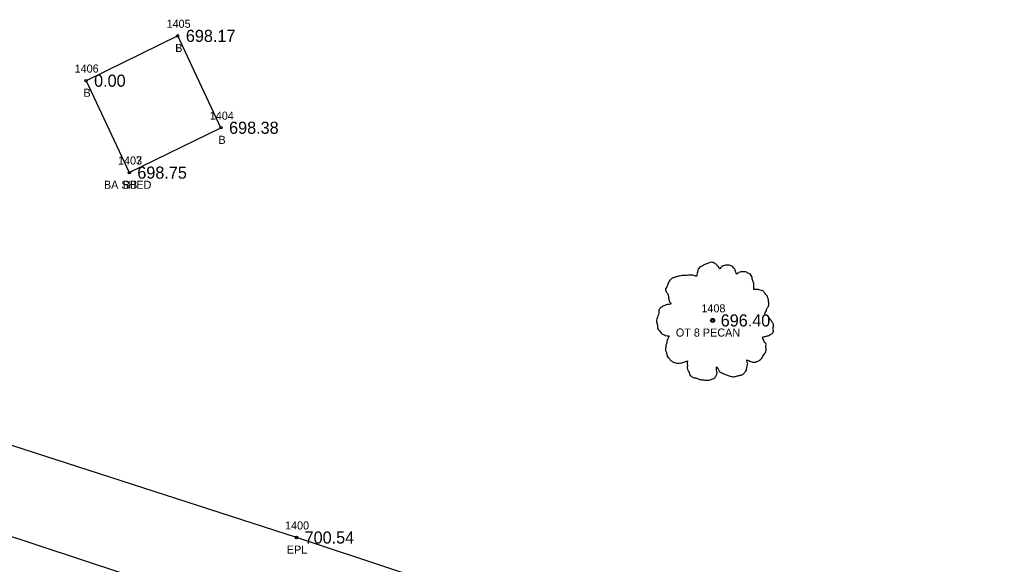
# Model space of a CAD drawing. Extents: x 1655137 to 1657928, y 1003994 to 1005407.
# Drawn here: x 1655718.8 to 1655840.3, y 1004839 to 1004906.5 of the extents above; entities that cross this region are included whole.
import ezdxf

# ---------------------------------------------------------------- set-up
doc = ezdxf.new("R2010")
doc.units = 0
for name, color, linetype in [('RD_EX_Bldg', 7, 'Continuous'), ('RD_EX_Bldg_txCode', 7, 'Continuous'), ('RD_EX_Road', 7, 'Continuous'), ('RD_EX_Road_txCode', 7, 'Continuous'), ('RD_EX_TX_Bldg_ELEV', 7, 'Continuous'), ('RD_EX_TX_Road_ELEV', 7, 'Continuous'), ('RD_EX_TX_VEG_ELEV', 7, 'Continuous'), ('RD_EX_VEG', 7, 'Continuous'), ('RD_EX_VEG_txCode', 7, 'Continuous'), ('RD_HC_Cl', 7, 'Continuous'), ('RD_SMD_Locator', 7, 'Continuous')]:
    doc.layers.add(name, color=color, linetype=linetype)

msp = doc.modelspace()

# ---------------------------------------------------------------- linework, layer by layer
at = {"layer": 'RD_EX_Bldg'}
msp.add_lwpolyline([(1655732.38, 1004887.51), (1655743.74, 1004893.07), (1655738.39, 1004904.45), (1655727.03, 1004898.9), (1655732.38, 1004887.51)], dxfattribs=at)
at = {"layer": 'RD_EX_Road'}
msp.add_lwpolyline([(1656365.12, 1004639.99), (1656336.04, 1004649.34), (1656302.55, 1004660.37), (1656279.15, 1004668.23), (1656240.07, 1004681.05), (1656188.23, 1004698.03), (1656166.72, 1004705.51), (1656141.16, 1004714.06), (1656093.11, 1004730.11), (1656044.16, 1004746.75), (1655996.36, 1004762.45), (1655947.2, 1004778.68), (1655899.09, 1004794.03), (1655850.62, 1004809.99), (1655801.91, 1004826.1), (1655753.09, 1004842.31), (1655704.25, 1004858.1)], dxfattribs=at)
at = {"layer": 'RD_EX_VEG'}
for centre, radius in [((1655804.6, 1004869.2), 0.25), ((1655804.59, 1004869.19), 0.0001)]:
    msp.add_circle(centre, radius, dxfattribs=at)
for points in [[(1655804.73, 1004876.37), (1655804.43, 1004876.4), (1655804.11, 1004876.3), (1655803.86, 1004876.2), (1655803.63, 1004876.12), (1655803.41, 1004876.02), (1655803.11, 1004875.85), (1655802.88, 1004875.65), (1655802.76, 1004875.4), (1655802.71, 1004875.17), (1655802.66, 1004874.9), (1655802.66, 1004874.72), (1655802.53, 1004874.7), (1655802.38, 1004874.72), (1655802.13, 1004874.8), (1655801.88, 1004874.8), (1655801.63, 1004874.8), (1655801.28, 1004874.77), (1655800.93, 1004874.77), (1655800.66, 1004874.72), (1655800.33, 1004874.67), (1655799.96, 1004874.55), (1655799.61, 1004874.42), (1655799.31, 1004874.17), (1655799.06, 1004873.7), (1655798.93, 1004873.35), (1655798.78, 1004873.1), (1655798.93, 1004872.65), (1655799.11, 1004872.3), (1655799.13, 1004872.1), (1655799.21, 1004871.67), (1655799.31, 1004871.45), (1655799.43, 1004871.25), (1655799.36, 1004871.22), (1655798.98, 1004871.17), (1655798.68, 1004871.07), (1655798.26, 1004870.85), (1655798.03, 1004870.62), (1655797.93, 1004870.3), (1655797.91, 1004869.95), (1655797.81, 1004869.75), (1655797.73, 1004869.47), (1655797.71, 1004869.4), (1655797.66, 1004869.07), (1655797.76, 1004868.62), (1655797.78, 1004868.27), (1655797.91, 1004868.05), (1655798.06, 1004867.88), (1655798.23, 1004867.63), (1655798.63, 1004867.4), (1655798.96, 1004867.3), (1655799.16, 1004867.28), (1655798.98, 1004866.78), (1655798.93, 1004866.43), (1655798.81, 1004866.03), (1655798.81, 1004865.95), (1655798.76, 1004865.48), (1655798.91, 1004865.15), (1655798.98, 1004864.78), (1655799.16, 1004864.55), (1655799.43, 1004864.25), (1655799.76, 1004864.03), (1655800.26, 1004863.9), (1655800.66, 1004863.93), (1655801.23, 1004864.1), (1655801.48, 1004864.18), (1655801.46, 1004864), (1655801.48, 1004863.63), (1655801.48, 1004863.2), (1655801.63, 1004862.88), (1655801.73, 1004862.6), (1655801.88, 1004862.35), (1655802.21, 1004862.13), (1655802.61, 1004862.05), (1655803.03, 1004861.9), (1655803.48, 1004861.83), (1655803.98, 1004861.8), (1655804.58, 1004861.95), (1655804.86, 1004862.08), (1655804.96, 1004862.25), (1655805.16, 1004862.63), (1655805.11, 1004862.85), (1655805.13, 1004863.45), (1655805.23, 1004863.28), (1655805.41, 1004862.93), (1655805.91, 1004862.63), (1655806.3, 1004862.45), (1655806.78, 1004862.3), (1655807.08, 1004862.23), (1655807.55, 1004862.3), (1655807.93, 1004862.38), (1655808.3, 1004862.5), (1655808.6, 1004862.78), (1655808.78, 1004863.05), (1655808.83, 1004863.33), (1655808.9, 1004863.7), (1655808.95, 1004863.88)], [(1655808.95, 1004863.88), (1655808.88, 1004864.05), (1655808.83, 1004864.3), (1655808.9, 1004864.28), (1655809.08, 1004864.23), (1655809.35, 1004864.1), (1655809.58, 1004864.03), (1655809.9, 1004864.05), (1655810.18, 1004864.15), (1655810.63, 1004864.43), (1655810.9, 1004864.9), (1655811.18, 1004865.3), (1655811.25, 1004865.63), (1655811.2, 1004865.85), (1655811.18, 1004866.35), (1655810.98, 1004866.6), (1655810.93, 1004866.73), (1655810.83, 1004867.13), (1655810.9, 1004867.18), (1655811.18, 1004867.23), (1655811.55, 1004867.35), (1655811.83, 1004867.48), (1655812.05, 1004867.65), (1655812.13, 1004867.88), (1655812.1, 1004868.27), (1655812.15, 1004868.67), (1655812.08, 1004868.82), (1655811.98, 1004868.97), (1655811.9, 1004869.17), (1655811.75, 1004869.32), (1655811.65, 1004869.47), (1655811.55, 1004869.57), (1655811.43, 1004869.72), (1655811.25, 1004869.85), (1655811.1, 1004869.9), (1655811.05, 1004870.05), (1655811.2, 1004870.25), (1655811.25, 1004870.35), (1655811.28, 1004870.57), (1655811.5, 1004870.92), (1655811.55, 1004871.32), (1655811.5, 1004871.75), (1655811.45, 1004872.02), (1655811.3, 1004872.3), (1655811.1, 1004872.55), (1655810.98, 1004872.72), (1655810.8, 1004872.85), (1655810.48, 1004872.97), (1655810.23, 1004873.02), (1655809.88, 1004873.02), (1655809.68, 1004873.07), (1655809.7, 1004873.12), (1655809.7, 1004873.27), (1655809.7, 1004873.55), (1655809.63, 1004874), (1655809.48, 1004874.5), (1655809.48, 1004874.52), (1655809.38, 1004874.77), (1655809.15, 1004874.97), (1655808.98, 1004875.07), (1655808.78, 1004875.2), (1655808.53, 1004875.22), (1655808.23, 1004875.22), (1655807.95, 1004875.17), (1655807.75, 1004875.07), (1655807.58, 1004874.95), (1655807.5, 1004875.1), (1655807.4, 1004875.4), (1655807.35, 1004875.55), (1655807.2, 1004875.72), (1655806.98, 1004875.92), (1655806.53, 1004876.05), (1655805.91, 1004875.97), (1655805.61, 1004875.77), (1655805.46, 1004875.6), (1655805.41, 1004875.72), (1655805.21, 1004875.92), (1655805.11, 1004876.1), (1655804.93, 1004876.22), (1655804.78, 1004876.32), (1655804.68, 1004876.37)]]:
    msp.add_spline(points, degree=3, dxfattribs=at)
at = {"layer": 'RD_HC_Cl'}
msp.add_line((1655701.51, 1004847.78), (1656069.26, 1004726.84), dxfattribs=at)
at = {"layer": 'RD_SMD_Locator'}
for centre in [(1655738.39, 1004904.45), (1655727.03, 1004898.9), (1655743.74, 1004893.07), (1655732.38, 1004887.51), (1655732.38, 1004887.51), (1655804.6, 1004869.2), (1655753.09, 1004842.31)]:
    msp.add_circle(centre, 0.15, dxfattribs=at)

# ---------------------------------------------------------------- texts
at = {"layer": 'RD_EX_Bldg_txCode'}
for s, p in [('1405', (1655737, 1004905.45)), ('B', (1655738.08, 1004902.45)), ('1406', (1655725.62, 1004899.9)), ('B', (1655726.72, 1004896.9)), ('1404', (1655742.35, 1004894.07)), ('B', (1655743.43, 1004891.07)), ('1403', (1655730.99, 1004888.51)), ('1407', (1655730.99, 1004888.51)), ('BA SHED', (1655729.25, 1004885.51)), ('BB', (1655731.6, 1004885.51))]:
    msp.add_text(s, height=1, dxfattribs=at).set_placement(p)
at = {"layer": 'RD_EX_Road_txCode'}
for s, p in [('1400', (1655751.67, 1004843.31)), ('EPL', (1655751.89, 1004840.31))]:
    msp.add_text(s, height=1, dxfattribs=at).set_placement(p)
at = {"layer": 'RD_EX_TX_Bldg_ELEV'}
for s, p in [('698.17', (1655739.39, 1004903.7)), ('0.00', (1655728.03, 1004898.15)), ('698.38', (1655744.74, 1004892.32)), ('698.75', (1655733.38, 1004886.76)), ('698.75', (1655733.38, 1004886.76))]:
    msp.add_text(s, height=1.5, dxfattribs=at).set_placement(p)
at = {"layer": 'RD_EX_TX_Road_ELEV'}
msp.add_text('700.54', height=1.5, dxfattribs=at).set_placement((1655754.09, 1004841.56))
at = {"layer": 'RD_EX_TX_VEG_ELEV'}
msp.add_text('696.40', height=1.5, dxfattribs=at).set_placement((1655805.6, 1004868.45))
at = {"layer": 'RD_EX_VEG_txCode'}
for s, p in [('1408', (1655803.21, 1004870.2)), ('OT 8 PECAN', (1655800.05, 1004867.2))]:
    msp.add_text(s, height=1, dxfattribs=at).set_placement(p)

doc.saveas('drawing.dxf')
